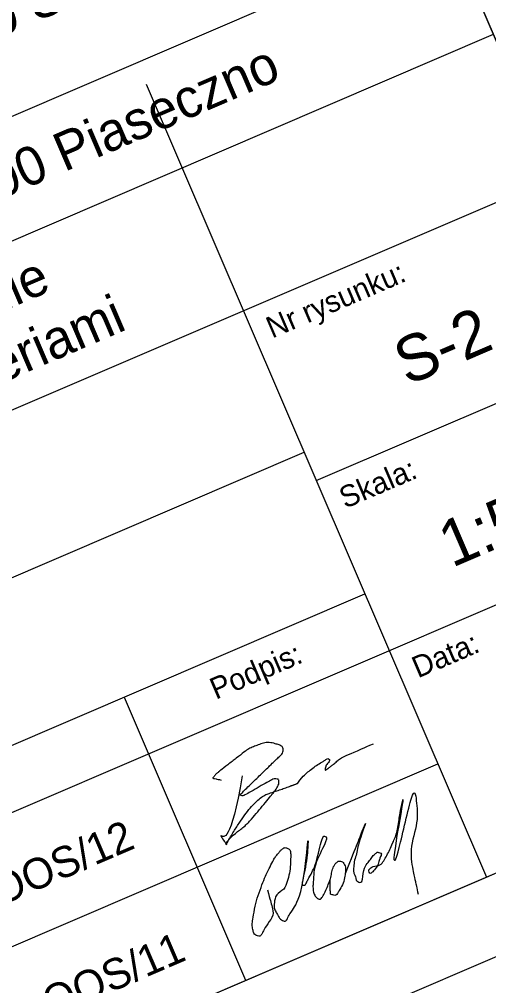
# Model space of a CAD drawing. Extents: x 7500108 to 7500715, y 5768804 to 5769157.
# Drawn here: x 7500642.87 to 7500658.1, y 5769014.08 to 5769045.44 of the extents above; entities that cross this region are included whole.
import ezdxf

# ---------------------------------------------------------------- set-up
doc = ezdxf.new("R2010")
doc.units = 0
for name, color, linetype in [('2_opisy_KD_etap1', 7, 'Continuous'), ('_Wydruk', 7, 'Continuous'), ('DZIALKI', 7, 'Continuous'), ('KLASOUZYTKI', 7, 'Continuous')]:
    doc.layers.add(name, color=color, linetype=linetype)

# ---------------------------------------------------------------- blocks, each defined once
blk = doc.blocks.new('_U2')
at = {"layer": '2_opisy_KD_etap1'}
for points, degree in [([(-5.09, 2.13), (-10.52, -4.72), (-11.31, -2.14), (-10.95, -4.55), (-11.09, -4.5), (-10.83, -4.22), (-10.68, -4.17), (-9.36, -3.72), (-7.98, -3.65), (-6.69, -3.18), (-5.57, -2.77), (-4.45, -2.34), (-3.33, -1.89), (-2.73, -1.64), (-2.17, -1.41), (-1.6, -1.03), (-1.52, -0.98), (-1.49, -0.88), (-1.45, -0.8), (-1.39, -0.68), (-1.29, -0.5), (-1.41, -0.38), (-1.73, -0.09), (-2.09, -0.11), (-2.44, -0.11), (-3.6, -0.09), (-4.77, -0.16), (-5.93, -0.14), (-6.01, -0.14), (-6.09, -0.14), (-6.16, -0.12), (-6.29, -0.09), (-6.54, 0.16), (-6.41, 0.19), (-4.72, 0.67), (-3, 1.14), (-1.29, 1.6), (-0.7, 1.76), (-0.11, 1.91), (0.48, 2.08), (0.73, 2.15), (0.97, 2.4), (1.04, 2.6), (1.14, 2.89), (0.86, 3.3), (0.54, 3.61), (-0.09, 4.22), (-0.74, 4.45), (-1.47, 4.56), (-2.09, 4.65), (-2.73, 4.72), (-3.35, 4.63), (-4.67, 4.43), (-5.99, 4.23), (-7.31, 4.02), (-7.46, 4), (-7.62, 3.97), (-7.77, 3.95), (-7.9, 3.93), (-8.02, 3.87), (-8.15, 3.8), (-8.25, 3.74), (-8.51, 3.69), (-8.43, 3.62), (-8.17, 3.39), (-7.92, 3.17), (-7.66, 2.95)], 3), ([(0.59, -2.08), (1.2, -1.74), (1.86, -1.55), (2.54, -1.42), (3.34, -1.27), (4.13, -1.24), (4.92, -1.21), (5.09, -1.2), (5.35, -1.14), (5.42, -1.25), (5.6, -1.51), (4.84, -1.77), (4.56, -2.04), (4.53, -2.08), (4.49, -2.12), (4.46, -2.16), (4.42, -2.19), (4.39, -2.31), (4.44, -2.31), (4.8, -2.29), (5.16, -2.23), (5.52, -2.18), (6.08, -2.1), (6.63, -1.9), (7.18, -1.95), (8.56, -2.08), (9.93, -2.2), (11.31, -2.33)], 3), ([(-10.95, -4.39), (-5.41, -1.01), (-1.26, -1.82), (0.59, -2.08)], 2)]:
    blk.add_open_spline(points, degree=degree, dxfattribs=at)
blk = doc.blocks.new('_U3')
at = {"layer": '2_opisy_KD_etap1'}
for points in [[(-9.26, 2.84), (-9.44, 2.14), (-9.62, 1.43), (-9.79, 0.73), (-10.07, -0.36), (-11.34, -0.88), (-12.33, -1.5), (-12.58, -1.66), (-12.96, -1.87), (-13.18, -1.61), (-13.33, -1.42), (-13.43, -1.21), (-13.39, -1.02), (-13.28, -0.47), (-13.01, 0.08), (-12.6, 0.59), (-11.62, 1.84), (-10.67, 2.8), (-9.53, 3.77), (-8.68, 4.48), (-7.82, 5.09), (-6.88, 5.7), (-6.47, 5.97), (-6, 6.15), (-5.56, 6.32), (-5.26, 6.44), (-4.81, 6.51), (-4.57, 6.23), (-4.31, 5.92), (-4.49, 5.44), (-4.67, 5.13), (-5.19, 4.23), (-5.83, 3.33), (-6.59, 2.56), (-7.35, 1.8), (-8.68, 1.89), (-9.34, 0.94), (-9.67, 0.47), (-9.68, -0.09), (-9.68, -0.61), (-9.68, -0.88), (-9.66, -1.17), (-9.5, -1.42), (-9.21, -1.86), (-8.51, -1.29), (-8.08, -1.07), (-5.65, 0.18), (-1.16, 6.81), (-2.32, 4.95), (-2.91, 4.02), (-4, 2.69), (-4.91, 1.64), (-4.95, 1.6), (-4.99, 1.56), (-5.02, 1.52), (-5.1, 1.43), (-5.13, 1.2), (-5.05, 1.16), (-4.8, 1.03), (-4.33, 1.43), (-4, 1.63), (-2.39, 2.6), (0.1, 5.57), (0.35, 5.2), (0.59, 4.84), (-2.5, 2.89), (-3.49, 1.34), (-3.79, 0.86), (-4.11, 0.41), (-4.31, -0.11), (-4.4, -0.35), (-4.4, -0.63), (-4.38, -0.88), (-4.36, -1), (-4.34, -1.1), (-4.26, -1.21), (-4.15, -1.34), (-3.97, -1.43), (-3.85, -1.36), (-3.2, -1.01), (-2.55, -0.52), (-1.95, 0), (-1.39, 0.47), (-1.02, 1.07), (-0.39, 1.5), (-0.24, 1.61), (-0.05, 1.63), (0.12, 1.66), (0.2, 1.68), (0.3, 1.7), (0.38, 1.64), (0.81, 1.3), (0.7, 0.53), (0.44, 0.13), (-0.03, -0.56), (-0.69, -1.17), (-1.51, -1.67), (-1.76, -1.82), (-2.1, -1.98), (-2.31, -1.76), (-2.45, -1.63), (-2.62, -1.46), (-2.54, -1.32), (-2.27, -0.82), (-2, -0.32), (-1.73, 0.18)], [(0.39, -0.04), (1.99, 1.27), (3.59, 2.59), (5.19, 3.9), (5.93, 4.51), (3.77, 2.61), (3.14, 1.88), (2.58, 1.23), (1.96, 0.68), (1.49, -0.08), (1.26, -0.46), (1.24, -0.88), (1.15, -1.28), (1.12, -1.39), (1.06, -1.52), (1.12, -1.62), (1.53, -2.38), (2.54, -0.66), (3.35, -0.32), (3.9, -0.08), (4.45, 0.2), (4.99, 0.29), (5.1, 0.31), (5.22, 0.22), (5.32, 0.12), (5.56, -0.14), (5.08, -0.45), (4.85, -0.69), (4.36, -1.19), (3.49, -1.59), (3.1, -1.62), (3, -1.62), (3.01, -1.16), (3.14, -1.11), (3.73, -0.92), (4.68, -1.38), (5.28, -1.04), (5.97, -0.65), (6.64, -0.17), (7.29, 0.32), (8.63, 1.32), (9.78, 3.01), (10.65, 4), (11.87, 5.39), (6.33, -1.48), (6.51, -1.64), (6.73, -1.82), (13.43, 5.79), (12.56, 3.65), (11.54, 1.16), (8.68, -1.39), (7.78, -4.37), (7.53, -5.18), (7.29, -5.99), (7.04, -6.81)]]:
    blk.add_open_spline(points, degree=3, dxfattribs=at)

msp = doc.modelspace()

# ---------------------------------------------------------------- linework, layer by layer
at = {"layer": '_Wydruk'}
msp.add_lwpolyline([(7500603.806, 5768994.339), (7500668.134, 5769021.941), (7500650.853, 5769062.216)], dxfattribs=at)
at = {"layer": 'DZIALKI'}
msp.add_lwpolyline([(7500108.062, 5768940.503), (7500612.863, 5769157.097), (7500671.417, 5769020.629), (7500166.617, 5768804.034)], close=True, dxfattribs=at)
at = {"layer": 'KLASOUZYTKI'}
for p, q in [((7500592.463, 5769020.775), (7500656.791, 5769048.376)), ((7500593.929, 5769017.358), (7500658.257, 5769044.959)), ((7500646.985, 5769043.335), (7500658.025, 5769017.603)), ((7500595.919, 5769012.719), (7500660.248, 5769040.32)), ((7500652.505, 5769030.469), (7500662.614, 5769034.806)), ((7500597.891, 5769008.124), (7500652.111, 5769031.388)), ((7500600.651, 5769001.691), (7500664.98, 5769029.292)), ((7500599.862, 5769003.529), (7500654.082, 5769026.793)), ((7500646.271, 5769023.441), (7500650.214, 5769014.252)), ((7500658.025, 5769017.603), (7500668.134, 5769021.941)), ((7500602.228, 5768998.015), (7500656.448, 5769021.279)), ((7500603.806, 5768994.339), (7500658.025, 5769017.603))]:
    msp.add_line(p, q, dxfattribs=at)
msp.add_lwpolyline([(7500603.806, 5768994.339), (7500668.134, 5769021.941), (7500653.956, 5769054.985), (7500589.627, 5769027.383)], close=True, dxfattribs=at)

# ---------------------------------------------------------------- block references
at = {"layer": '2_opisy_KD_etap1', "xscale": 0.258048, "yscale": 0.25804800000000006, "rotation": 28.969310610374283}
for name, p in [('_U2', (7500651.517, 5769021.044)), ('_U3', (7500653.371, 5769017.704))]:
    msp.add_blockref(name, p, dxfattribs=at)

# ---------------------------------------------------------------- texts
at = {"layer": 'KLASOUZYTKI'}
for s, height, p in [('ul. Jana Brzechwy 16, 96-100 Skierniewice', 1.25, (7500622.743, 5769036.486)), ('BURMISTRZ m. PIASECZNO ul. Kościuszki 5; 05-500 Piaseczno', 1.25, (7500606.854, 5769024.402)), ('Remont ul. 11 Listopada w Piasecznie', 1.25, (7500617.906, 5769025.475)), ('Nr rysunku:', 0.7, (7500651.072, 5769035.077)), ('na odc. od ul. Zagłoby do ul. Pod Bateriami', 1.25, (7500617.027, 5769022.786)), ('S-2', 1.5, (7500655.459, 5769033.54)), ('Skala:', 0.7, (7500653.443, 5769029.552)), ('1:500', 1.5, (7500656.909, 5769027.633)), ('Data:', 0.7, (7500655.804, 5769024.049)), ('Podpis:', 0.7, (7500649.246, 5769023.354)), ('MAZ/0056/POOS/12', 1, (7500635.406, 5769013.723)), ('MAZ/0240/POOS/11', 1, (7500637.064, 5769010.09))]:
    msp.add_text(s, height=height, rotation=23.2227, dxfattribs=at).set_placement(p)

doc.saveas('drawing.dxf')
